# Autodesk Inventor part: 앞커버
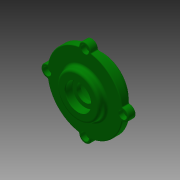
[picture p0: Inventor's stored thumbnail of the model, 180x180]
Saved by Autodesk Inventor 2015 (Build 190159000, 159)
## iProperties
Created: 2016-05
Part Number: 앞커버
Document SubType Name: Modeling
Designer: mduedu
Density: 2.71 g/cm^3
Material: 알루미늄 6061
Appearance: 진녹색
Author: mduedu
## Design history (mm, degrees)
sketch "스케치1"
  geometry: C1 r 32 at (0, 0); C2 r 44 at (0, 0); 1 further point
  constraints: 2 centre point, 2 coincident
  dimensions: "d33" = 88 diameter of C2; "d34" = 64 diameter of C1
extrude "돌출1" new body sketch "스케치1" distance "d0" = 8; taper "d1" = 0 deg
extrude "돌출2" join sketch "스케치1" distance "d2" = 8; taper "d3" = 0 deg; dims "d35" = 12, "d36" = 0
sketch "스케치6"
  geometry: C1 r 25 at (0, 0); 2 further points
  constraints: 2 coincident, 1 centre point
  dimensions: "d42" = 50 diameter of C1
extrude "돌출4" join sketch "스케치6" distance "d43" = 8; taper "d44" = 0 deg
sketch "스케치9"
  geometry: C1 r 7 at (0, 44); 2 further points
  constraints: 2 vertical alignment, 1 centre point, 1 other
  dimensions: "d70" = 14 diameter of C1
extrude "돌출5" join sketch "스케치9" stored distance "d71" = 10; taper "d72" = 0 deg
fillet "모깎기9" dims "d76" = 1
sketch "스케치10"
  geometry: C1 r 25 at (0, 0) reference; A1 r 1 centre (-44.284, 7.995) between (-44.249, 6.996) and (-43.3, 7.817) reference; A2 r 7 centre (-44, 0) between (-44.249, 6.996) and (-44.249, -6.996) reference; A3 r 1 centre (-44.284, -7.995) between (-43.3, -7.817) and (-44.249, -6.996) reference; A4 r 44 centre (0, 0) between (-43.3, -7.817) and (-7.817, -43.3) reference; A5 r 1 centre (-7.995, -44.284) between (-6.996, -44.249) and (-7.817, -43.3) reference; A6 r 7 centre (0, -44) between (-6.996, -44.249) and (6.996, -44.249) reference; A7 r 1 centre (7.995, -44.284) between (7.817, -43.3) and (6.996, -44.249) reference; A8 r 1 centre (7.995, 44.284) between (6.996, 44.249) and (7.817, 43.3) reference; A9 r 7 centre (0, 44) between (6.996, 44.249) and (-6.996, 44.249) reference; A10 r 1 centre (-7.995, 44.284) between (-7.817, 43.3) and (-6.996, 44.249) reference; A11 r 7 centre (44, 0) between (44.249, -6.996) and (44.249, 6.996) reference; A12 r 44 centre (0, 0) between (-7.817, 43.3) and (-43.3, 7.817) reference; A13 r 44 centre (0, 0) between (7.817, -43.3) and (43.3, -7.817) reference; A14 r 1 centre (44.284, -7.995) between (44.249, -6.996) and (43.3, -7.817) reference; A15 r 1 centre (44.284, 7.995) between (43.3, 7.817) and (44.249, 6.996) reference; A16 r 44 centre (0, 0) between (43.3, 7.817) and (7.817, 43.3) reference; 4 further points
  constraints: 3 coincident
hole "구멍3" sketch "스케치10" at (0, 44), (-44, 0), (0, -44), (44, 0) diameter "d77" = 5.5; stored, may be unused: countersink angle "d81" = 90 deg, drill point angle "d83" = 118 deg; dims "d78" = 6, "d79" = 9.5, "d80" = 5.4, "d82" = 8
fillet "모깎기10" dims "d84" = 1
fillet "모깎기7" dims "d68" = 3
fillet "모깎기8" dims "d69" = 3
sketch "스케치4"
  geometry: L1 (0, -12)-(0, 16); L2 (-20, -12)-(-20, 0); L3 (-20, 0)-(-15, 0); L4 (-15, 0)-(-15, 3); L5 (-15, 3)-(-10, 3); L6 (-10, 3)-(-10, 7.7); L7 (-10, 7.7)-(-15, 7.7); L8 (-15, 7.7)-(-15, 16); L9 (32, -12)-(-32, -12) reference; L10 (25, 16)-(-25, 16) reference; 1 further point
  constraints: 16 end point, 6 parallel, 3 point on line, 2 midpoint, 1 perpendicular, 1 vertical
  dimensions: "d15" = 40 diameter of L2 L1; "d16" = 30 diameter of L8 L1; "d18" = 12 distance of L2.start L2.end; "d19" = 3 distance of L3.end L4.end; "d20" = 30 diameter of L4 L1; "d21" = 20 diameter of L6 L1; "d45" = 8.3 distance of L7.end L8.end
revolve "회전1" sketch "스케치4" stored, may be unused: angle "d22" = 90 deg
fillet "모깎기2" dims "d23" = 3
fillet "모깎기3" dims "d24" = 0.3
chamfer "모따기2" distance "d46" = 1; stored, may be unused: second distance "d47" = 2, angle "d48" = 45 deg
chamfer "모따기3" distance "d64" = 0.8; stored, may be unused: second distance "d65" = 2, angle "d66" = 30 deg
node "솔리드1"
pattern_circular "원형 패턴1" dims angle "d74" = 360 deg
node "투영된 루프1"
